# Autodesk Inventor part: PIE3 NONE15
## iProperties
Shininess: 64.0
Length Units: 11269
Angle Units: 11279
Time Units: 11290
Mass Units: 11286
Length Display Precision: 3
Angle Display Precision: 2
Compacted: True
Part Number: PIE3 NONE15
Document SubType Name: Modeling
Created: 2004-08
Designer: John Blackburn
Manufacturer: Standard
Standards Organization: Custom
Density: 0.0
Volumn: 0.0
Area: 0.0
PropertySet Name: Model Information
Control State: 0
Master: False
Checked Out: False
Author: John Blackburn
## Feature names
1. Erst1
